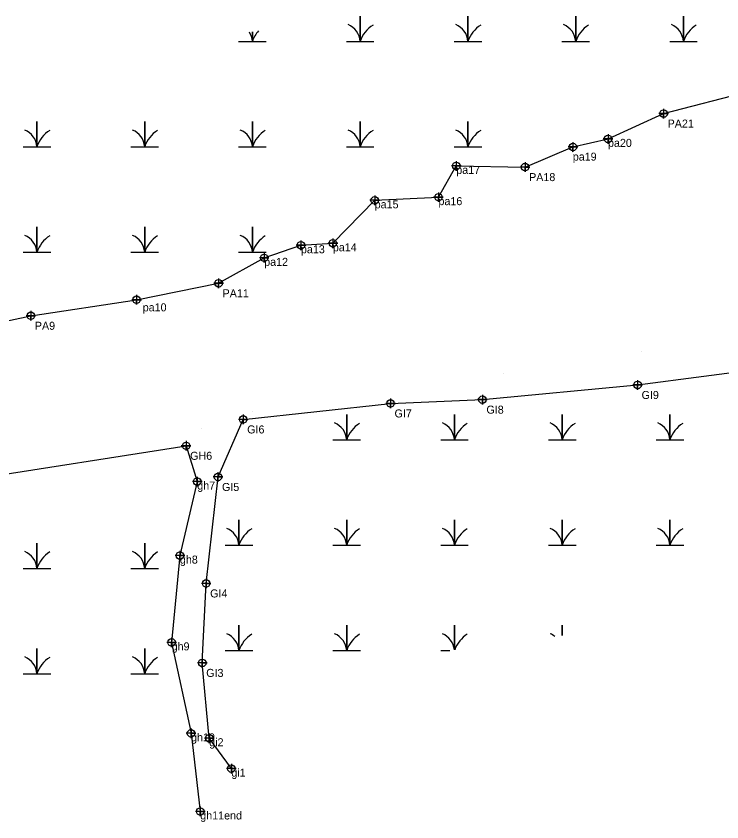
# Model space of a CAD drawing. Extents: x 2072529 to 2268796, y 436423 to 470406.
# Drawn here: x 2186456 to 2186896, y 453160 to 453663 of the extents above; entities that cross this region are included whole.
import ezdxf

# ---------------------------------------------------------------- set-up
doc = ezdxf.new("R2010")
doc.units = 0
for name, color, linetype in [('Exist Environmental Wetland Boundary', 7, 'Continuous'), ('Exist Environmental Wetland Boundary Cogo Comment', 7, 'Continuous'), ('Exist Environmental Wetland Boundary Cogo Point CELL', 7, 'Continuous'), ('Old_Level_20', 7, 'Continuous')]:
    doc.layers.add(name, color=color, linetype=linetype)

msp = doc.modelspace()

# ---------------------------------------------------------------- linework, layer by layer
at = {"layer": 'Exist Environmental Wetland Boundary'}
for points in [[(2186859.95, 453605.41), (2186859.95, 453599.41), (2186859.95, 453602.41), (2186862.95, 453602.41), (2186856.95, 453602.41)], [(2186825.25, 453589.6), (2186825.25, 453583.6), (2186825.25, 453586.6), (2186828.25, 453586.6), (2186822.25, 453586.6)], [(2186803.32, 453584.54), (2186803.32, 453578.54), (2186803.32, 453581.54), (2186806.32, 453581.54), (2186800.32, 453581.54)], [(2186730.56, 453572.74), (2186730.56, 453566.74), (2186730.56, 453569.74), (2186733.56, 453569.74), (2186727.56, 453569.74)], [(2186773.5, 453571.98), (2186773.5, 453565.98), (2186773.5, 453568.98), (2186776.5, 453568.98), (2186770.5, 453568.98)], [(2186719.43, 453553.22), (2186719.43, 453547.22), (2186719.43, 453550.22), (2186722.43, 453550.22), (2186716.43, 453550.22)], [(2186679.64, 453551.24), (2186679.64, 453545.24), (2186679.64, 453548.24), (2186682.64, 453548.24), (2186676.64, 453548.24)], [(2186633.62, 453523.2), (2186633.62, 453517.2), (2186633.62, 453520.2), (2186636.62, 453520.2), (2186630.62, 453520.2)], [(2186653.53, 453524.44), (2186653.53, 453518.44), (2186653.53, 453521.44), (2186656.53, 453521.44), (2186650.53, 453521.44)], [(2186610.66, 453515.33), (2186610.66, 453509.33), (2186610.66, 453512.33), (2186613.66, 453512.33), (2186607.66, 453512.33)], [(2186582.21, 453499.45), (2186582.21, 453493.45), (2186582.21, 453496.45), (2186585.21, 453496.45), (2186579.21, 453496.45)], [(2186531, 453489.21), (2186531, 453483.21), (2186531, 453486.21), (2186534, 453486.21), (2186528, 453486.21)], [(2186465.03, 453479.17), (2186465.03, 453473.17), (2186465.03, 453476.17), (2186468.03, 453476.17), (2186462.03, 453476.17)], [(2186843.7, 453435.98), (2186843.7, 453429.98), (2186843.7, 453432.98), (2186846.7, 453432.98), (2186840.7, 453432.98)], [(2186746.86, 453426.8), (2186746.86, 453420.8), (2186746.86, 453423.8), (2186749.87, 453423.8), (2186743.87, 453423.8)], [(2186689.52, 453424.44), (2186689.52, 453418.44), (2186689.52, 453421.44), (2186692.52, 453421.44), (2186686.52, 453421.44)], [(2186597.55, 453414.45), (2186597.55, 453408.45), (2186597.55, 453411.45), (2186600.55, 453411.45), (2186594.55, 453411.45)], [(2186561.95, 453397.99), (2186561.95, 453391.99), (2186561.95, 453394.99), (2186564.95, 453394.99), (2186558.95, 453394.99)], [(2186581.84, 453378.54), (2186581.84, 453372.54), (2186581.84, 453375.54), (2186584.84, 453375.54), (2186578.84, 453375.54)], [(2186568.89, 453375.66), (2186568.89, 453369.66), (2186568.89, 453372.66), (2186571.89, 453372.66), (2186565.89, 453372.66)], [(2186558.07, 453329.45), (2186558.07, 453323.45), (2186558.07, 453326.45), (2186561.07, 453326.45), (2186555.07, 453326.45)], [(2186574.44, 453312.06), (2186574.44, 453306.06), (2186574.44, 453309.06), (2186577.44, 453309.06), (2186571.44, 453309.06)], [(2186552.91, 453275.26), (2186552.91, 453269.26), (2186552.91, 453272.26), (2186555.91, 453272.26), (2186549.91, 453272.26)], [(2186571.99, 453262.45), (2186571.99, 453256.45), (2186571.99, 453259.45), (2186574.99, 453259.45), (2186568.99, 453259.45)], [(2186565.03, 453218.48), (2186565.03, 453212.48), (2186565.03, 453215.48), (2186568.03, 453215.48), (2186562.03, 453215.48)], [(2186576.37, 453215.42), (2186576.37, 453209.42), (2186576.37, 453212.42), (2186579.37, 453212.42), (2186573.37, 453212.42)], [(2186590.17, 453196.44), (2186590.17, 453190.44), (2186590.17, 453193.44), (2186593.17, 453193.44), (2186587.17, 453193.44)], [(2186570.77, 453169.7), (2186570.77, 453163.7), (2186570.77, 453166.7), (2186573.77, 453166.7), (2186567.77, 453166.7)]]:
    msp.add_lwpolyline(points, dxfattribs=at)
for centre in [(2186859.95, 453602.41), (2186825.25, 453586.6), (2186803.32, 453581.54), (2186730.56, 453569.74), (2186773.5, 453568.98), (2186719.43, 453550.22), (2186679.64, 453548.24), (2186633.62, 453520.2), (2186653.53, 453521.44), (2186610.66, 453512.33), (2186582.21, 453496.45), (2186531, 453486.21), (2186465.03, 453476.17), (2186843.7, 453432.98), (2186746.86, 453423.8), (2186689.52, 453421.44), (2186597.55, 453411.45), (2186561.95, 453394.99), (2186581.84, 453375.54), (2186568.89, 453372.66), (2186558.07, 453326.45), (2186574.44, 453309.06), (2186552.91, 453272.26), (2186571.99, 453259.45), (2186565.03, 453215.48), (2186576.37, 453212.42), (2186590.17, 453193.44), (2186570.77, 453166.7)]:
    msp.add_circle(centre, 2.34, dxfattribs=at)
at = {"layer": 'Exist Environmental Wetland Boundary Cogo Point CELL'}
for points in [[(2186661.98, 453647.47), (2186670.58, 453647.47), (2186670.58, 453663.21)], [(2186670.58, 453663.21), (2186670.58, 453647.47), (2186679.19, 453647.47)], [(2186729.23, 453647.47), (2186737.83, 453647.47), (2186737.83, 453663.25), (2186737.83, 453647.47), (2186746.44, 453647.47)], [(2186796.48, 453647.47), (2186805.08, 453647.47), (2186805.08, 453663.25), (2186805.08, 453647.47), (2186813.69, 453647.47)], [(2186863.73, 453647.47), (2186872.33, 453647.47), (2186872.33, 453663.25), (2186872.33, 453647.47), (2186880.94, 453647.47)], [(2186594.73, 453647.47), (2186603.33, 453647.47), (2186603.33, 453653.44)], [(2186603.33, 453653.44), (2186603.33, 453647.47), (2186611.94, 453647.47)], [(2186460.23, 453581.67), (2186468.83, 453581.67), (2186468.83, 453597.45), (2186468.83, 453581.67), (2186477.44, 453581.67)], [(2186527.48, 453581.67), (2186536.08, 453581.67), (2186536.08, 453597.45), (2186536.08, 453581.67), (2186544.69, 453581.67)], [(2186594.73, 453581.67), (2186603.33, 453581.67), (2186603.33, 453597.45), (2186603.33, 453581.67), (2186611.94, 453581.67)], [(2186661.98, 453581.67), (2186670.58, 453581.67), (2186670.58, 453597.45), (2186670.58, 453581.67), (2186679.19, 453581.67)], [(2186729.23, 453581.67), (2186737.83, 453581.67), (2186737.83, 453597.45), (2186737.83, 453581.67), (2186746.44, 453581.67)], [(2186460.23, 453515.87), (2186468.83, 453515.87), (2186468.83, 453531.65), (2186468.83, 453515.87), (2186477.44, 453515.87)], [(2186527.48, 453515.87), (2186536.08, 453515.87), (2186536.08, 453531.65), (2186536.08, 453515.87), (2186544.69, 453515.87)], [(2186594.73, 453515.87), (2186603.33, 453515.87), (2186603.33, 453531.65), (2186603.33, 453515.87), (2186611.94, 453515.87)], [(2186653.57, 453398.77), (2186662.17, 453398.77), (2186662.17, 453414.55), (2186662.17, 453398.77), (2186670.77, 453398.77)], [(2186720.82, 453398.77), (2186729.42, 453398.77), (2186729.42, 453414.55), (2186729.42, 453398.77), (2186738.02, 453398.77)], [(2186788.07, 453398.77), (2186796.67, 453398.77), (2186796.67, 453414.55), (2186796.67, 453398.77), (2186805.27, 453398.77)], [(2186855.32, 453398.77), (2186863.92, 453398.77), (2186863.92, 453414.55), (2186863.92, 453398.77), (2186872.52, 453398.77)], [(2186586.32, 453332.97), (2186594.92, 453332.97), (2186594.92, 453348.75), (2186594.92, 453332.97), (2186603.52, 453332.97)], [(2186653.57, 453332.97), (2186662.17, 453332.97), (2186662.17, 453348.75), (2186662.17, 453332.97), (2186670.77, 453332.97)], [(2186720.82, 453332.97), (2186729.42, 453332.97), (2186729.42, 453348.75), (2186729.42, 453332.97), (2186738.02, 453332.97)], [(2186788.07, 453332.97), (2186796.67, 453332.97), (2186796.67, 453348.75), (2186796.67, 453332.97), (2186805.27, 453332.97)], [(2186855.32, 453332.97), (2186863.92, 453332.97), (2186863.92, 453348.75), (2186863.92, 453332.97), (2186872.52, 453332.97)], [(2186460.23, 453318.47), (2186468.83, 453318.47), (2186468.83, 453334.25), (2186468.83, 453318.47), (2186477.44, 453318.47)], [(2186527.48, 453318.47), (2186536.08, 453318.47), (2186536.08, 453334.25), (2186536.08, 453318.47), (2186544.69, 453318.47)], [(2186586.32, 453267.17), (2186594.92, 453267.17), (2186594.92, 453282.95), (2186594.92, 453267.17), (2186603.52, 453267.17)], [(2186653.57, 453267.17), (2186662.17, 453267.17), (2186662.17, 453282.95), (2186662.17, 453267.17), (2186670.77, 453267.17)], [(2186729.42, 453267.55), (2186729.42, 453282.95), (2186729.42, 453267.55)], [(2186796.67, 453276.46), (2186796.67, 453282.95), (2186796.67, 453276.46)], [(2186460.23, 453252.67), (2186468.83, 453252.67), (2186468.83, 453268.45), (2186468.83, 453252.67), (2186477.44, 453252.67)], [(2186527.48, 453252.67), (2186536.08, 453252.67), (2186536.08, 453268.45), (2186536.08, 453252.67), (2186544.69, 453252.67)], [(2186720.82, 453267.17), (2186726.62, 453267.17)]]:
    msp.add_lwpolyline(points, dxfattribs=at)
for centre, radius, start, end in [((2186658.32, 453646.58), 12.3, 4.1403, 67.535), ((2186688.83, 453641.41), 19.22, 122.1274, 161.6222), ((2186725.57, 453646.58), 12.3, 4.1403, 67.535), ((2186756.08, 453641.41), 19.22, 122.1274, 161.6222), ((2186792.82, 453646.58), 12.3, 4.1403, 67.535), ((2186823.33, 453641.41), 19.22, 122.1274, 161.6222), ((2186860.07, 453646.58), 12.3, 4.1403, 67.535), ((2186890.58, 453641.41), 19.22, 122.1274, 161.6222), ((2186591.07, 453646.58), 12.3, 4.1403, 32.3279), ((2186621.58, 453641.41), 19.22, 139.0897, 161.6222), ((2186456.57, 453580.78), 12.3, 4.1403, 67.535), ((2186523.82, 453580.78), 12.3, 4.1403, 67.535), ((2186591.07, 453580.78), 12.3, 4.1403, 67.535), ((2186658.32, 453580.78), 12.3, 4.1403, 67.535), ((2186725.57, 453580.78), 12.3, 4.1403, 67.535), ((2186487.08, 453575.61), 19.22, 122.1274, 161.6222), ((2186554.33, 453575.61), 19.22, 122.1274, 161.6222), ((2186621.58, 453575.61), 19.22, 122.1274, 161.6222), ((2186688.83, 453575.61), 19.22, 122.1274, 161.6222), ((2186756.08, 453575.61), 19.22, 122.1274, 161.6222), ((2186456.57, 453514.98), 12.3, 4.1403, 67.535), ((2186487.08, 453509.81), 19.22, 122.1274, 161.6222), ((2186523.82, 453514.98), 12.3, 4.1403, 67.535), ((2186554.33, 453509.81), 19.22, 122.1274, 161.6222), ((2186591.07, 453514.98), 12.3, 4.1403, 67.535), ((2186621.58, 453509.81), 19.22, 122.1274, 161.6222), ((2186649.9, 453397.88), 12.3, 4.1403, 67.535), ((2186680.41, 453392.71), 19.22, 122.1274, 161.6222), ((2186717.15, 453397.88), 12.3, 4.1403, 67.535), ((2186747.66, 453392.71), 19.22, 122.1274, 161.6222), ((2186784.4, 453397.88), 12.3, 4.1403, 67.535), ((2186814.91, 453392.71), 19.22, 122.1274, 161.6222), ((2186851.65, 453397.88), 12.3, 4.1403, 67.535), ((2186882.16, 453392.71), 19.22, 122.1274, 161.6222), ((2186582.65, 453332.08), 12.3, 4.1403, 67.535), ((2186613.16, 453326.91), 19.22, 122.1274, 161.6222), ((2186649.9, 453332.08), 12.3, 4.1403, 67.535), ((2186680.41, 453326.91), 19.22, 122.1274, 161.6222), ((2186717.15, 453332.08), 12.3, 4.1403, 67.535), ((2186747.66, 453326.91), 19.22, 122.1274, 161.6222), ((2186784.4, 453332.08), 12.3, 4.1403, 67.535), ((2186814.91, 453326.91), 19.22, 122.1274, 161.6222), ((2186851.65, 453332.08), 12.3, 4.1403, 67.535), ((2186882.16, 453326.91), 19.22, 122.1274, 161.6222), ((2186456.57, 453317.58), 12.3, 4.1403, 67.535), ((2186487.08, 453312.41), 19.22, 122.1274, 161.6222), ((2186523.82, 453317.58), 12.3, 4.1403, 67.535), ((2186554.33, 453312.41), 19.22, 122.1274, 161.6222), ((2186582.65, 453266.28), 12.3, 4.1403, 67.535), ((2186613.16, 453261.11), 19.22, 122.1274, 161.6222), ((2186649.9, 453266.28), 12.3, 4.1403, 67.535), ((2186680.41, 453261.11), 19.22, 122.1274, 161.6222), ((2186717.15, 453266.28), 12.3, 5.9125, 67.535), ((2186747.66, 453261.11), 19.22, 122.1274, 160.3533), ((2186784.4, 453266.28), 12.3, 51.4009, 67.535), ((2186456.57, 453251.78), 12.3, 4.1403, 67.535), ((2186487.08, 453246.61), 19.22, 122.1274, 161.6222), ((2186523.82, 453251.78), 12.3, 4.1403, 67.535), ((2186554.33, 453246.61), 19.22, 122.1274, 161.6222)]:
    msp.add_arc(centre, radius, start, end, dxfattribs=at)
at = {"layer": 'Old_Level_20'}
for p, q in [((2186874.86, 453598.82), (2186874.86, 453598.82)), ((2186825.25, 453586.6), (2186825.25, 453586.6)), ((2186803.26, 453578.02), (2186803.26, 453578.02)), ((2186730.56, 453569.74), (2186730.56, 453569.74)), ((2186779.02, 453562.9), (2186779.02, 453562.9)), ((2186679.64, 453548.24), (2186679.64, 453548.24)), ((2186719.43, 453550.22), (2186719.43, 453550.22)), ((2186633.62, 453520.2), (2186633.62, 453520.2)), ((2186653.53, 453521.44), (2186653.53, 453521.44)), ((2186610.66, 453512.33), (2186610.66, 453512.33)), ((2186589.98, 453492.33), (2186589.98, 453492.33)), ((2186534.87, 453483.93), (2186534.87, 453483.93)), ((2186468.72, 453469.48), (2186468.72, 453469.48)), ((2186846.29, 453453.96), (2186846.29, 453453.96)), ((2186760.27, 453440.34), (2186760.27, 453440.34)), ((2186603.13, 453416.61), (2186603.13, 453416.61)), ((2186571.75, 453405.62), (2186571.75, 453405.62)), ((2186583.92, 453376.7), (2186583.92, 453376.7)), ((2186568.89, 453372.66), (2186568.89, 453372.66)), ((2186558.07, 453326.45), (2186558.07, 453326.45)), ((2186569.12, 453326.29), (2186569.12, 453326.29)), ((2186552.91, 453272.26), (2186552.91, 453272.26)), ((2186572.64, 453270.73), (2186572.64, 453270.73)), ((2186565.03, 453215.48), (2186565.03, 453215.48)), ((2186576.37, 453212.42), (2186576.37, 453212.42)), ((2186590.17, 453193.44), (2186590.17, 453193.44)), ((2186570.77, 453166.7), (2186570.77, 453166.7))]:
    msp.add_line(p, q, dxfattribs=at)
for points in [[(2186136.42, 453345.7), (2186123.85, 453385.42), (2186156.47, 453404.68), (2186186.24, 453405.63), (2186223.09, 453417.02), (2186269.09, 453435.52), (2186331.65, 453447.63), (2186403.33, 453466.98), (2186436.62, 453470.04), (2186465.03, 453476.17), (2186531, 453486.21), (2186582.21, 453496.45), (2186610.66, 453512.33), (2186633.62, 453520.2), (2186653.53, 453521.44), (2186679.64, 453548.24), (2186719.43, 453550.22), (2186730.56, 453569.74), (2186773.57, 453568.96), (2186803.32, 453581.55), (2186825.25, 453586.6), (2186859.95, 453602.41), (2186914.68, 453616.56)], [(2186590.17, 453193.44), (2186576.37, 453212.42), (2186571.99, 453259.45), (2186574.44, 453309.06), (2186581.86, 453375.55), (2186597.55, 453411.45), (2186689.52, 453421.44), (2186746.86, 453423.8), (2186843.7, 453432.98), (2186967.92, 453449.19), (2187070.14, 453462.52), (2187156.63, 453463.76), (2187237.25, 453469.29), (2187303.93, 453487.14), (2187368.79, 453485.11), (2187436.86, 453480.5), (2187462.85, 453481.82), (2187471.15, 453496.67), (2187476.13, 453504.11)], [(2186136.42, 453345.7), (2186155.01, 453329.55), (2186227.4, 453339.07), (2186359.15, 453366.24), (2186428.91, 453374.15), (2186561.95, 453394.99), (2186568.89, 453372.66), (2186558.07, 453326.45), (2186552.91, 453272.26), (2186565.03, 453215.48), (2186570.77, 453166.7)]]:
    msp.add_lwpolyline(points, dxfattribs=at)

# ---------------------------------------------------------------- texts
at = {"layer": 'Exist Environmental Wetland Boundary Cogo Comment'}
for s, p in [('PA21', (2186862.45, 453593.66)), ('pa20', (2186825.25, 453581.6)), ('pa19', (2186803.26, 453573.02)), ('pa17', (2186730.56, 453564.74)), ('PA18', (2186776, 453560.23)), ('pa15', (2186679.64, 453543.24)), ('pa16', (2186719.43, 453545.22)), ('pa13', (2186633.62, 453515.2)), ('pa14', (2186653.53, 453516.44)), ('pa12', (2186610.66, 453507.33)), ('PA11', (2186584.71, 453487.7)), ('pa10', (2186534.87, 453478.93)), ('PA9', (2186467.53, 453467.42)), ('GI9', (2186846.2, 453424.23)), ('GI7', (2186692.02, 453412.69)), ('GI8', (2186749.37, 453415.05)), ('GI6', (2186600.05, 453402.7)), ('GH6', (2186564.45, 453386.24)), ('gh7', (2186568.89, 453367.66)), ('GI5', (2186584.34, 453366.79)), ('gh8', (2186558.07, 453321.45)), ('GI4', (2186576.94, 453300.31)), ('gh9', (2186552.91, 453267.26)), ('GI3', (2186574.49, 453250.7)), ('gh10', (2186565.03, 453210.48)), ('gi2', (2186576.37, 453207.42)), ('gi1', (2186590.17, 453188.44)), ('gh11end', (2186570.77, 453161.7))]:
    msp.add_text(s, height=5, dxfattribs=at).set_placement(p)

doc.saveas('drawing.dxf')
